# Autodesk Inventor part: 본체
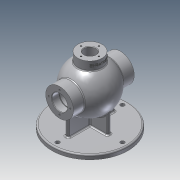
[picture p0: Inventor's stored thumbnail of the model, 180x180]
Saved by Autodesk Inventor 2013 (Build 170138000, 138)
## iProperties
Created: 2020-08
Part Number: 본체
Material: 알루미늄 6061
Document SubType Name: Sheet Metal
Designer: CADCOM
Density: 1 g/cm^3
Sheet Metal Rule: Default_mm
Author: CADCOM
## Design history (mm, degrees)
sketch "스케치2"
  geometry: L1 (-27.958, -45.026)-(27.958, 45.026); A1 r 53 centre (0, 0) between (-27.958, -45.026) and (27.958, 45.026); 1 further point
  constraints: 2 end point, 2 point on circle, 1 centre point, 1 coincident, 1 midpoint
  dimensions: "d3" = 106 diameter of A1
revolve "회전2" sketch "스케치2" stored, may be unused: angle "d4" = 90 deg
node "작업 평면1"
sketch "스케치3"
  geometry: C1 r 31 at (0, 0); 1 further point
  constraints: 1 centre point, 1 coincident
  dimensions: "d6" = 62 diameter of C1
extrude "돌출1" join sketch "스케치3" stored distance "d7" = 10; taper "d8" = 0 deg
node "작업 평면2"
sketch "스케치4"
  geometry: C1 r 31 at (0, 0); 1 further point
  constraints: 1 centre point, 1 coincident
  dimensions: "d10" = 62 diameter of C1
extrude "돌출2" join sketch "스케치4" stored distance "d11" = 10; taper "d12" = 0 deg
sketch "스케치5"
  geometry: L1 (32.002, -28.72)-(-32.002, 28.72); A1 r 43 centre (0, 0) between (32.002, -28.72) and (-32.002, 28.72); 1 further point
  constraints: 2 end point, 2 point on circle, 1 centre point, 1 coincident, 1 midpoint
  dimensions: "d13" = 86 diameter of A1
revolve "회전3" sketch "스케치5" stored, may be unused: angle "d14" = 90 deg
sketch "스케치6"
  geometry: C1 r 31 at (0, 0) reference; C2 r 17.5 at (0, 0)
  constraints: 1 centre point, 1 coincident
  dimensions: "d15" = 35 diameter of C2
extrude "돌출3" cut sketch "스케치6" stored distance "d16" = 10; taper "d17" = 0 deg
node "작업 평면3"
sketch "스케치7"
  geometry: C1 r 27 at (0, 0); 1 further point
  constraints: 1 centre point, 1 coincident
  dimensions: "d19" = 54 diameter of C1
extrude "돌출4" join sketch "스케치7" stored distance "d20" = 10; taper "d21" = 0 deg
sketch "스케치8"
  geometry: C1 r 27 at (0, 0) reference; C2 r 13 at (0, 0)
  constraints: 1 centre point, 1 coincident
  dimensions: "d22" = 26 diameter of C2
extrude "돌출5" cut sketch "스케치8" stored distance "d23" = 10; taper "d24" = 0 deg
sketch "스케치9" dims "d25" = 48
  geometry: C1 r 17.5 at (0, 0) reference; C2 r 31 at (0, 0) reference; 2 further points
  constraints: 2 vertical alignment, 1 coincident, 2 other
hole "구멍1" sketch "스케치9" at (0, 24) diameter "d26" = 3.242; stored, may be unused: countersink angle "d30" = 90 deg, drill point angle "d32" = 118 deg; dims "d27" = 12, "d28" = 4, "d29" = 2, "d31" = 15
sketch "스케치10" dims "d36" = 40
  geometry: C1 r 13 at (0, 0) reference; C2 r 27 at (0, 0) reference; 2 further points
  constraints: 2 vertical alignment, 1 coincident, 2 other
hole "구멍2" sketch "스케치10" at (0, 20) diameter "d37" = 3.242; stored, may be unused: countersink angle "d41" = 90 deg, drill point angle "d43" = 118 deg; dims "d38" = 12, "d39" = 4, "d40" = 2, "d42" = 15
node "작업 평면4"
sketch "스케치11"
  geometry: C1 r 85 at (0, 0); 1 further point
  constraints: 1 centre point, 1 coincident
  dimensions: "d48" = 170 diameter of C1
extrude "돌출6" join sketch "스케치11" distance "d49" = 10; taper "d50" = 0 deg
sketch "스케치12"
  geometry: L1 (-52, 4)-(52, 4); L2 (52, 4)-(52, -4); L3 (52, -4)-(-52, -4); L4 (-52, -4)-(-52, 4); L5 (-4, 43)-(4, 43); L6 (4, 43)-(4, -43); L7 (4, -43)-(-4, -43); L8 (-4, -43)-(-4, 43); C1 r 85 at (0, 0) reference
  constraints: 16 end point, 4 parallel, 2 horizontal, 2 perpendicular
  dimensions: "d51" = 104 distance of L2.end L3.end; "d52" = 8 distance of L1.end L2.end; "d53" = 52 distance from line of L2 C1.centre; "d54" = 4 distance from line of C1.centre L1; "d55" = 8 distance of L6.end L7.end; "d56" = 86 distance of L5.end L6.end; "d57" = 43 distance from line of C1.centre L5; "d58" = 4 distance from line of C1.centre L6
extrude "돌출7" join sketch "스케치12" stored distance "d59" = 10; taper "d60" = 0 deg
sketch "스케치13" dims "d61" = 145
  geometry: C1 r 85 at (0, 0) reference; 2 further points
  constraints: 2 vertical alignment, 1 coincident, 2 other
hole "구멍3" sketch "스케치13" at (0, 72.5) diameter "d62" = 9; stored, may be unused: countersink angle "d66" = 90 deg, drill point angle "d68" = 118 deg; dims "d63" = 12, "d64" = 4, "d65" = 2, "d67" = 15
node "작업 평면5"
sketch "스케치14"
  geometry: L1 (-27, 65)-(27, 65) reference; L2 (-27, 45.607)-(27, 45.607) reference; L3 (27, 65)-(27, 45.607) reference; L4 (-27, 65)-(-27, 45.607) reference; 2 further points
  constraints: 1 other
  dimensions: "d74" = 9 distance from line of point (0, 56) L1; "d75" = 27 distance from line of L4 point (0, 56)
feature "엠보싱1" sketch "스케치14" dims "d76" = 0.5, "d77" = 0, "SeamGap" = 0.01
node "작업 평면6"
sketch "스케치15"
  geometry: L1 (67.238, -75)-(67.238, -85) reference; L2 (67.238, -85)-(-67.238, -85) reference; L3 (-67.238, -85)-(-67.238, -75) reference; L4 (-67.238, -75)-(-4, -75) reference; L5 (-4, -75)-(4, -75) reference; L6 (4, -75)-(67.238, -75) reference; L7 (-4, -75)-(-4, -30.741) reference; L8 (4, -30.741)-(4, -75) reference; C1 r 17.5 at (0, 0) reference; C2 r 18.5 at (0, 0); A1 r 31 centre (0, 0) between (-4, -30.741) and (4, -30.741) reference; A2 r 31 centre (0, 0) between (4, -30.741) and (-4, -30.741) reference; 1 further point
  constraints: 1 centre point, 1 coincident
  dimensions: "d79" = 37 diameter of C2
extrude "돌출8" cut sketch "스케치15" distance "d80" = 1.75; taper "d81" = 0 deg
chamfer "모따기1" distance "d82" = 1; stored, may be unused: second distance "d83" = 2, angle "d84" = 45 deg
fillet "모깎기1" dims "d85" = 3
fillet "모깎기2" dims "d86" = 3
fillet "모깎기3" dims "d87" = 3
fillet "모깎기4" dims "d88" = 3
fillet "모깎기5" dims "d89" = 3
node "솔리드2"
pattern_circular "원형 패턴1" dims angle "d34" = 360 deg
pattern_circular "원형 패턴2" dims angle "d45" = 360 deg
mirror "대칭1"
pattern_circular "원형 패턴3" dims angle "d70" = 360 deg
node "절단 모서리 투영1"
other parameters: "Thickness" = 0.5, "BendRadius" = 0.5 (= Thickness), "BendReliefWidth" = 0.5 (= Thickness), "BendReliefDepth" = 0.25 (= 0.5 x Thickness), "CornerReliefSize" = 2 (= 4 x Thickness), "MinimumRemnant" = 1 (= 2 x Thickness), "TransitionRadius" = 0.5 (= BendRadius), "JacobiRadiusSize" = 0.5 (= BendRadius), "GapSize" = 0.5 (= Thickness), "d5" = 68, "d9" = -68, "d18" = 65, "d47" = -85, "d72" = 38, "d78" = -16
